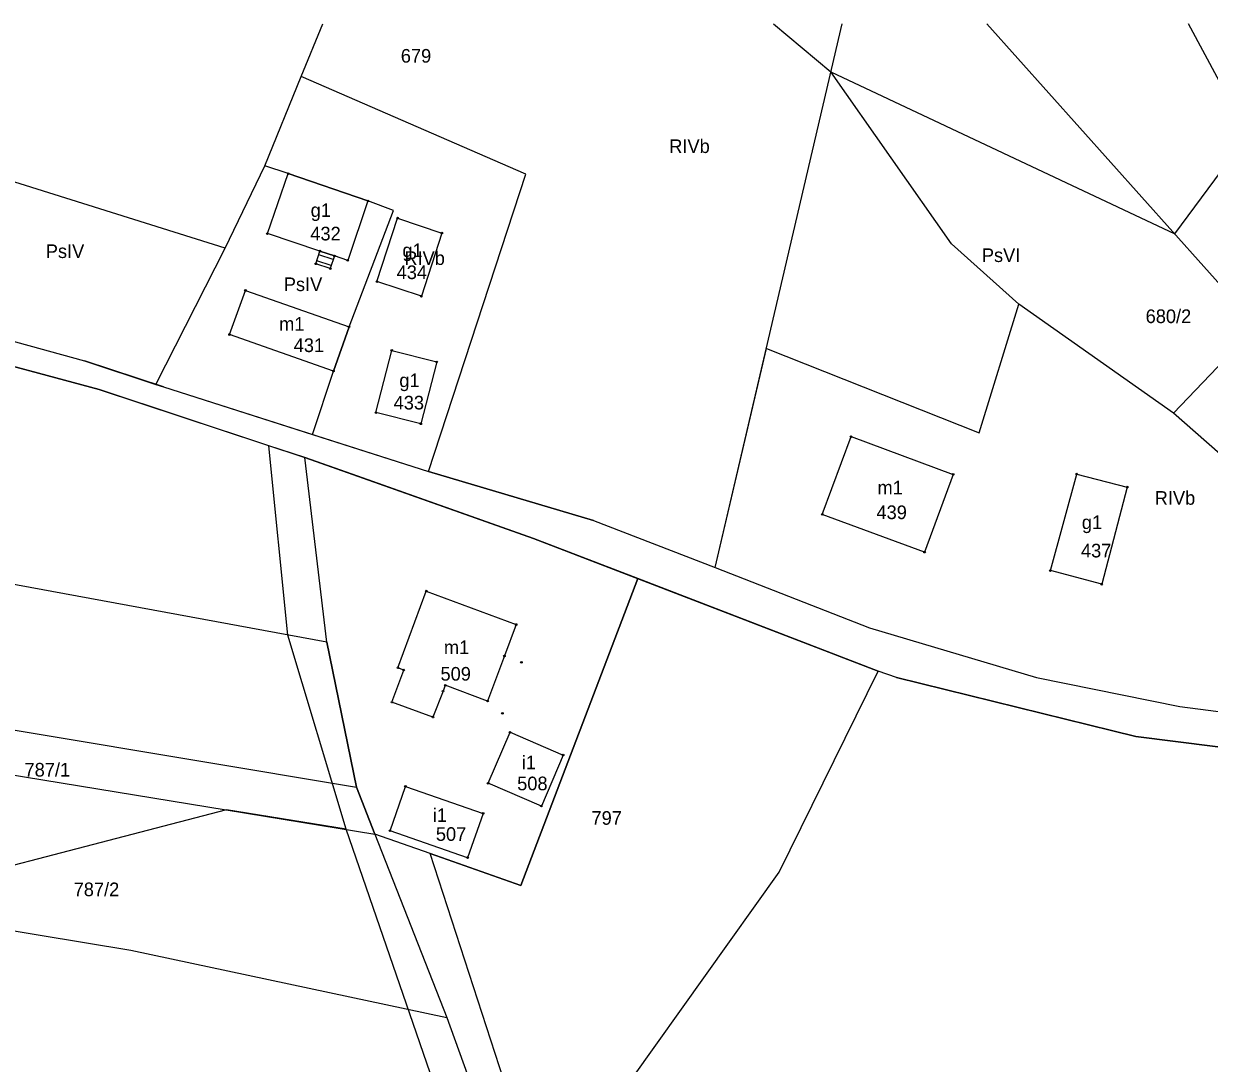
# Model space of a CAD drawing. Extents: x 7498273 to 7499989, y 5499795 to 5500810.
# Drawn here: x 7499410.3 to 7499540.8, y 5500695.1 to 5500809.6 of the extents above; entities that cross this region are included whole.
import ezdxf

# ---------------------------------------------------------------- set-up
doc = ezdxf.new("R2010")
doc.units = 0
for name, color, linetype in [('209-oznaczenie konturu klasyfikacyjnego', 7, 'Continuous'), ('211-numer działki ewidencyjnej', 7, 'Continuous'), ('217-kontur klasyfikacyjny', 7, 'Continuous'), ('218-kontur użytku gruntowego', 7, 'Continuous'), ('219-działka ewidencyjna', 7, 'Continuous'), ('312-budynek ewidencyjny', 7, 'Continuous'), ('312-oznaczenie budynku ewidencyjnego', 7, 'Continuous'), ('312-oznaczenie budynku ewidencyjnego-Atr117', 7, 'Continuous'), ('352-schody', 7, 'Continuous'), ('Punkt budynku', 7, 'Continuous')]:
    doc.layers.add(name, color=color, linetype=linetype)

# ---------------------------------------------------------------- blocks, each defined once
blk = doc.blocks.new('PUNKTBUD')
blk.add_circle((0, 0), 0.09)

msp = doc.modelspace()

# ---------------------------------------------------------------- linework, layer by layer
at = {"layer": '217-kontur klasyfikacyjny'}
for points in [[(7499440.86, 5500803.75), (7499443.237, 5500809.555)], [(7499492.851, 5500809.555), (7499499.14, 5500804.25)], [(7499545.08, 5500797.34), (7499538.502, 5500809.555)], [(7499436.83, 5500793.91), (7499440.86, 5500803.75)], [(7499465.57, 5500793), (7499440.86, 5500803.75)], [(7499499.14, 5500804.25), (7499537, 5500786.42)], [(7499512.42, 5500785.31), (7499499.14, 5500804.25)], [(7499537, 5500786.42), (7499545.08, 5500797.34)], [(7499432.49, 5500784.86), (7499397.94, 5500795.67)], [(7499536.85, 5500766.69), (7499564.25, 5500795.32)], [(7499432.49, 5500784.86), (7499436.83, 5500793.91)], [(7499439.42, 5500793.05), (7499436.83, 5500793.91)], [(7499448.19, 5500790.04), (7499439.42, 5500793.05)], [(7499454.86, 5500760.25), (7499465.57, 5500793)], [(7499451.01, 5500788.99), (7499448.19, 5500790.04)], [(7499446.11, 5500776.18), (7499451.01, 5500788.99)], [(7499424.84, 5500769.85), (7499432.49, 5500784.86)], [(7499519.85, 5500778.69), (7499512.42, 5500785.31)], [(7499390.96, 5500779.61), (7499417, 5500772.43)], [(7499515.49, 5500764.51), (7499519.85, 5500778.69)], [(7499536.85, 5500766.69), (7499519.85, 5500778.69)], [(7499444.4, 5500771.32), (7499446.11, 5500776.18)], [(7499418.6, 5500769.27), (7499402.77, 5500773.53)], [(7499486.42, 5500749.69), (7499492.05, 5500773.81)], [(7499492.05, 5500773.81), (7499515.49, 5500764.51)], [(7499417, 5500772.43), (7499424.84, 5500769.85)], [(7499442.08, 5500764.33), (7499444.4, 5500771.32)], [(7499437.29, 5500763.1), (7499418.6, 5500769.27)], [(7499424.84, 5500769.85), (7499425.67, 5500769.58)], [(7499425.67, 5500769.58), (7499442.08, 5500764.33)], [(7499544.41, 5500760.05), (7499536.85, 5500766.69)], [(7499442.08, 5500764.33), (7499454.86, 5500760.25)], [(7499439.39, 5500742.25), (7499437.29, 5500763.1)], [(7499441.23, 5500761.8), (7499437.29, 5500763.1)], [(7499443.65, 5500741.47), (7499441.23, 5500761.8)], [(7499454.86, 5500760.25), (7499473.01, 5500754.88)], [(7499473.01, 5500754.88), (7499486.42, 5500749.69)], [(7499486.42, 5500749.69), (7499503.42, 5500743.06)], [(7499477.9, 5500748.47), (7499465.03, 5500714.67)], [(7499504.37, 5500738.28), (7499477.9, 5500748.47)], [(7499503.42, 5500743.06), (7499521.78, 5500737.58)], [(7499445.79, 5500720.87), (7499439.39, 5500742.25)], [(7499446.92, 5500725.52), (7499443.65, 5500741.47)], [(7499506.36, 5500737.6), (7499504.37, 5500738.28)], [(7499525.14, 5500732.96), (7499506.36, 5500737.6)], [(7499521.78, 5500737.58), (7499537.58, 5500734.4)], [(7499537.58, 5500734.4), (7499548.9, 5500732.93)], [(7499532.73, 5500731.09), (7499525.14, 5500732.96)], [(7499554.57, 5500728.32), (7499532.73, 5500731.09)], [(7499448.96, 5500720.35), (7499446.92, 5500725.52)], [(7499432.61, 5500723.02), (7499388.37, 5500711.5)], [(7499445.79, 5500720.87), (7499432.61, 5500723.02)], [(7499456.51, 5500689.82), (7499445.79, 5500720.87)], [(7499455.04, 5500718.2), (7499448.96, 5500720.35)], [(7499463.14, 5500693.24), (7499455.04, 5500718.2)], [(7499465.03, 5500714.67), (7499455.04, 5500718.2)]]:
    msp.add_lwpolyline(points, dxfattribs=at)
at = {"layer": '218-kontur użytku gruntowego'}
for points in [[(7499440.86, 5500803.75), (7499443.237, 5500809.555)], [(7499492.851, 5500809.555), (7499499.14, 5500804.25)], [(7499545.08, 5500797.34), (7499538.502, 5500809.555)], [(7499436.83, 5500793.91), (7499440.86, 5500803.75)], [(7499465.57, 5500793), (7499440.86, 5500803.75)], [(7499499.14, 5500804.25), (7499537, 5500786.42)], [(7499512.42, 5500785.31), (7499499.14, 5500804.25)], [(7499537, 5500786.42), (7499545.08, 5500797.34)], [(7499432.49, 5500784.86), (7499397.94, 5500795.67)], [(7499536.85, 5500766.69), (7499564.25, 5500795.32)], [(7499432.49, 5500784.86), (7499436.83, 5500793.91)], [(7499439.42, 5500793.05), (7499436.83, 5500793.91)], [(7499448.19, 5500790.04), (7499439.42, 5500793.05)], [(7499454.86, 5500760.25), (7499465.57, 5500793)], [(7499451.01, 5500788.99), (7499448.19, 5500790.04)], [(7499446.11, 5500776.18), (7499451.01, 5500788.99)], [(7499424.84, 5500769.85), (7499432.49, 5500784.86)], [(7499519.85, 5500778.69), (7499512.42, 5500785.31)], [(7499390.96, 5500779.61), (7499417, 5500772.43)], [(7499515.49, 5500764.51), (7499519.85, 5500778.69)], [(7499536.85, 5500766.69), (7499519.85, 5500778.69)], [(7499444.4, 5500771.32), (7499446.11, 5500776.18)], [(7499418.6, 5500769.27), (7499402.77, 5500773.53)], [(7499486.42, 5500749.69), (7499492.05, 5500773.81)], [(7499492.05, 5500773.81), (7499515.49, 5500764.51)], [(7499417, 5500772.43), (7499424.84, 5500769.85)], [(7499442.08, 5500764.33), (7499444.4, 5500771.32)], [(7499437.29, 5500763.1), (7499418.6, 5500769.27)], [(7499424.84, 5500769.85), (7499425.67, 5500769.58)], [(7499425.67, 5500769.58), (7499442.08, 5500764.33)], [(7499544.41, 5500760.05), (7499536.85, 5500766.69)], [(7499442.08, 5500764.33), (7499454.86, 5500760.25)], [(7499439.39, 5500742.25), (7499437.29, 5500763.1)], [(7499441.23, 5500761.8), (7499437.29, 5500763.1)], [(7499443.65, 5500741.47), (7499441.23, 5500761.8)], [(7499446.45, 5500759.96), (7499441.23, 5500761.8)], [(7499454.86, 5500760.25), (7499473.01, 5500754.88)], [(7499466.41, 5500752.9), (7499446.45, 5500759.96)], [(7499473.01, 5500754.88), (7499486.42, 5500749.69)], [(7499477.9, 5500748.47), (7499466.41, 5500752.9)], [(7499486.42, 5500749.69), (7499503.42, 5500743.06)], [(7499465.03, 5500714.67), (7499477.9, 5500748.47)], [(7499504.37, 5500738.28), (7499477.9, 5500748.47)], [(7499503.42, 5500743.06), (7499521.78, 5500737.58)], [(7499445.79, 5500720.87), (7499439.39, 5500742.25)], [(7499446.92, 5500725.52), (7499443.65, 5500741.47)], [(7499506.36, 5500737.6), (7499504.37, 5500738.28)], [(7499525.14, 5500732.96), (7499506.36, 5500737.6)], [(7499521.78, 5500737.58), (7499537.58, 5500734.4)], [(7499537.58, 5500734.4), (7499548.9, 5500732.93)], [(7499532.73, 5500731.09), (7499525.14, 5500732.96)], [(7499554.57, 5500728.32), (7499532.73, 5500731.09)], [(7499448.96, 5500720.35), (7499446.92, 5500725.52)], [(7499432.61, 5500723.02), (7499388.37, 5500711.5)], [(7499445.79, 5500720.87), (7499432.61, 5500723.02)], [(7499456.51, 5500689.82), (7499445.79, 5500720.87)], [(7499455.04, 5500718.2), (7499448.96, 5500720.35)], [(7499463.14, 5500693.24), (7499455.04, 5500718.2)], [(7499455.04, 5500718.2), (7499465.03, 5500714.67)]]:
    msp.add_lwpolyline(points, dxfattribs=at)
at = {"layer": '219-działka ewidencyjna'}
for points in [[(7499486.42, 5500749.69), (7499500.383, 5500809.555)], [(7499516.319, 5500809.555), (7499581.17, 5500737.03)], [(7499390.96, 5500779.61), (7499417, 5500772.43)], [(7499402.77, 5500773.53), (7499418.6, 5500769.27)], [(7499425.67, 5500769.58), (7499417, 5500772.43)], [(7499418.6, 5500769.27), (7499441.23, 5500761.8)], [(7499425.67, 5500769.58), (7499454.86, 5500760.25)], [(7499443.65, 5500741.47), (7499441.23, 5500761.8)], [(7499441.23, 5500761.8), (7499466.41, 5500752.9)], [(7499473.01, 5500754.88), (7499454.86, 5500760.25)], [(7499473.01, 5500754.88), (7499486.42, 5500749.69)], [(7499443.65, 5500741.47), (7499382.11, 5500752.81)], [(7499466.41, 5500752.9), (7499504.37, 5500738.28)], [(7499486.42, 5500749.69), (7499503.42, 5500743.06)], [(7499503.42, 5500743.06), (7499521.78, 5500737.58)], [(7499443.65, 5500741.47), (7499446.92, 5500725.52)], [(7499493.47, 5500716.14), (7499504.37, 5500738.28)], [(7499506.36, 5500737.6), (7499504.37, 5500738.28)], [(7499506.36, 5500737.6), (7499532.73, 5500731.09)], [(7499521.78, 5500737.58), (7499537.58, 5500734.4)], [(7499393.52, 5500734.43), (7499446.92, 5500725.52)], [(7499537.58, 5500734.4), (7499548.9, 5500732.93)], [(7499532.73, 5500731.09), (7499554.57, 5500728.32)], [(7499391.98, 5500729.67), (7499448.96, 5500720.35)], [(7499446.92, 5500725.52), (7499448.96, 5500720.35)], [(7499448.96, 5500720.35), (7499456.89, 5500700.16)], [(7499477.25, 5500693.42), (7499493.47, 5500716.14)], [(7499401.65, 5500710.96), (7499422.11, 5500707.58)], [(7499422.11, 5500707.58), (7499456.89, 5500700.16)], [(7499456.89, 5500700.16), (7499459.58, 5500692.65)]]:
    msp.add_lwpolyline(points, dxfattribs=at)
at = {"layer": '312-budynek ewidencyjny'}
for points in [[(7499437.12, 5500786.45), (7499439.42, 5500793.05)], [(7499439.42, 5500793.05), (7499448.19, 5500790.04)], [(7499448.19, 5500790.04), (7499445.97, 5500783.5)], [(7499449.18, 5500781.16), (7499451.46, 5500788.16)], [(7499451.46, 5500788.16), (7499456.33, 5500786.51)], [(7499442.91, 5500784.52), (7499437.12, 5500786.45)], [(7499456.33, 5500786.51), (7499454.07, 5500779.56)], [(7499444.51, 5500783.99), (7499442.91, 5500784.52)], [(7499445.97, 5500783.5), (7499444.51, 5500783.99)], [(7499454.07, 5500779.56), (7499449.18, 5500781.16)], [(7499432.96, 5500775.34), (7499434.71, 5500780.19)], [(7499434.71, 5500780.19), (7499446.11, 5500776.18)], [(7499446.11, 5500776.18), (7499444.4, 5500771.32)], [(7499444.4, 5500771.32), (7499432.96, 5500775.34)], [(7499449.07, 5500766.74), (7499450.82, 5500773.59)], [(7499450.82, 5500773.59), (7499455.76, 5500772.32)], [(7499455.76, 5500772.32), (7499454.01, 5500765.51)], [(7499454.01, 5500765.51), (7499449.07, 5500766.74)], [(7499498.21, 5500755.54), (7499501.37, 5500764.1)], [(7499501.37, 5500764.1), (7499512.61, 5500759.94)], [(7499512.61, 5500759.94), (7499509.46, 5500751.38)], [(7499523.31, 5500749.36), (7499526.21, 5500759.98)], [(7499526.21, 5500759.98), (7499531.78, 5500758.54)], [(7499531.78, 5500758.54), (7499528.96, 5500747.85)], [(7499509.46, 5500751.38), (7499498.21, 5500755.54)], [(7499528.96, 5500747.85), (7499523.31, 5500749.36)], [(7499451.5, 5500738.65), (7499454.62, 5500747.1)], [(7499454.62, 5500747.1), (7499464.51, 5500743.41)], [(7499464.51, 5500743.41), (7499463.22, 5500739.96)], [(7499463.22, 5500739.96), (7499461.37, 5500734.99)], [(7499450.84, 5500734.87), (7499452.13, 5500738.4)], [(7499452.13, 5500738.4), (7499451.5, 5500738.65)], [(7499456.71, 5500736.73), (7499456.46, 5500736.08)], [(7499461.37, 5500734.99), (7499456.71, 5500736.73)], [(7499456.46, 5500736.08), (7499455.35, 5500733.22)], [(7499455.35, 5500733.22), (7499450.84, 5500734.87)], [(7499461.42, 5500725.94), (7499463.83, 5500731.55)], [(7499463.83, 5500731.55), (7499469.68, 5500729.05)], [(7499469.68, 5500729.05), (7499467.28, 5500723.43)], [(7499450.63, 5500720.72), (7499452.32, 5500725.6)], [(7499452.32, 5500725.6), (7499460.87, 5500722.63)], [(7499467.28, 5500723.43), (7499461.42, 5500725.94)], [(7499460.87, 5500722.63), (7499459.17, 5500717.75)], [(7499459.17, 5500717.75), (7499450.63, 5500720.72)]]:
    msp.add_lwpolyline(points, dxfattribs=at)
at = {"layer": '352-schody'}
msp.add_lwpolyline([(7499442.45, 5500783.12), (7499442.91, 5500784.52), (7499444.51, 5500783.99), (7499444.05, 5500782.59)], close=True, dxfattribs=at)
msp.add_lwpolyline([(7499442.45, 5500783.12), (7499442.91, 5500784.52), (7499444.51, 5500783.99), (7499444.05, 5500782.59)], close=True, dxfattribs=at)
for points in [[(7499444.379, 5500783.591), (7499442.778, 5500784.118)], [(7499444.161, 5500782.926), (7499442.559, 5500783.453)]]:
    msp.add_lwpolyline(points, dxfattribs=at)

# ---------------------------------------------------------------- block references
at = {"layer": 'Punkt budynku'}
for p in [(7499439.42, 5500793.05), (7499448.19, 5500790.04), (7499451.46, 5500788.16), (7499437.12, 5500786.45), (7499456.33, 5500786.51), (7499442.91, 5500784.52), (7499444.51, 5500783.99), (7499445.97, 5500783.5), (7499442.45, 5500783.12), (7499444.05, 5500782.59), (7499449.18, 5500781.16), (7499434.71, 5500780.19), (7499454.07, 5500779.56), (7499446.11, 5500776.18), (7499432.96, 5500775.34), (7499450.82, 5500773.59), (7499455.76, 5500772.32), (7499444.4, 5500771.32), (7499449.07, 5500766.74), (7499454.01, 5500765.51), (7499501.37, 5500764.1), (7499512.61, 5500759.94), (7499526.21, 5500759.98), (7499531.78, 5500758.54), (7499498.21, 5500755.54), (7499509.46, 5500751.38), (7499523.31, 5500749.36), (7499454.62, 5500747.1), (7499528.96, 5500747.85), (7499464.51, 5500743.41), (7499463.22, 5500739.96), (7499465.09, 5500739.26), (7499451.5, 5500738.65), (7499452.13, 5500738.4), (7499456.71, 5500736.73), (7499456.46, 5500736.08), (7499450.84, 5500734.87), (7499461.37, 5500734.99), (7499455.35, 5500733.22), (7499463, 5500733.64), (7499463.83, 5500731.55), (7499469.68, 5500729.05), (7499452.32, 5500725.6), (7499461.42, 5500725.94), (7499467.28, 5500723.43), (7499460.87, 5500722.63), (7499450.63, 5500720.72), (7499459.17, 5500717.75)]:
    msp.add_blockref('PUNKTBUD', p, dxfattribs=at)

# ---------------------------------------------------------------- texts
at = {"layer": '209-oznaczenie konturu klasyfikacyjnego'}
for s, p in [('RIVb', (7499481.36, 5500795.32)), ('PsIV', (7499412.73, 5500783.76)), ('PsVI', (7499515.77, 5500783.32)), ('RIVb', (7499452.2, 5500783)), ('PsIV', (7499438.93, 5500780.12)), ('RIVb', (7499534.8, 5500756.6))]:
    msp.add_text(s, height=1.5, dxfattribs=at).set_placement(p)
at = {"layer": '211-numer działki ewidencyjnej'}
for s, p in [('679', (7499451.81, 5500805.27)), ('680/2', (7499533.8, 5500776.6)), ('787/1', (7499410.39, 5500726.68)), ('797', (7499472.8, 5500721.37)), ('787/2', (7499415.8, 5500713.51))]:
    msp.add_text(s, height=1.5, dxfattribs=at).set_placement(p)
at = {"layer": '312-oznaczenie budynku ewidencyjnego'}
for s, p in [('432', (7499441.85, 5500785.7)), ('434', (7499451.35, 5500781.44)), ('431', (7499440.02, 5500773.41)), ('433', (7499451.02, 5500767.09)), ('439', (7499504.17, 5500755.02)), ('437', (7499526.68, 5500750.8)), ('509', (7499456.18, 5500737.24)), ('508', (7499464.62, 5500725.17)), ('507', (7499455.67, 5500719.6))]:
    msp.add_text(s, height=1.5, dxfattribs=at).set_placement(p)
at = {"layer": '312-oznaczenie budynku ewidencyjnego-Atr117'}
for s, p in [('g1', (7499441.889, 5500788.28)), ('g1', (7499451.989, 5500783.86)), ('m1', (7499438.415, 5500775.76)), ('g1', (7499451.649, 5500769.55)), ('m1', (7499504.285, 5500757.74)), ('g1', (7499526.779, 5500753.92)), ('m1', (7499456.555, 5500740.16)), ('i1', (7499465.132, 5500727.49)), ('i1', (7499455.332, 5500721.68))]:
    msp.add_text(s, height=1.5, dxfattribs=at).set_placement(p)

doc.saveas('drawing.dxf')
